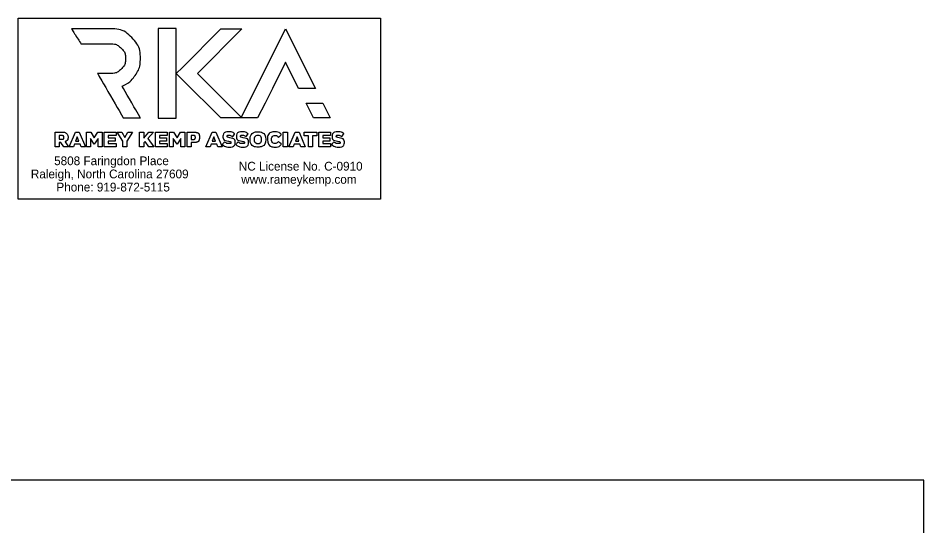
# Model space of a CAD drawing. Extents: x 573078 to 573131.9, y -55221.3 to -55195.5.
# Drawn here: x 573104.51 to 573112.01, y -55199.68 to -55195.47 of the extents above; entities that cross this region are included whole.
import ezdxf

# ---------------------------------------------------------------- set-up
doc = ezdxf.new("R2010")
doc.units = 0
for name, color, linetype in [('Old_Level_60', 7, 'Continuous'), ('Old_Level_61', 7, 'Continuous'), ('Old_Level_62', 7, 'Continuous'), ('Old_Level_63', 7, 'Continuous'), ('Sheet Plan CELL', 7, 'Continuous'), ('Sheet Plot Border Inside CELL', 7, 'Continuous')]:
    doc.layers.add(name, color=color, linetype=linetype)

msp = doc.modelspace()

# ---------------------------------------------------------------- linework, layer by layer
at = {"layer": 'Old_Level_60'}
for p, q in [((573105.8216, -55195.5551), (573105.6738, -55195.5551)), ((573105.6738, -55195.5551), (573105.6738, -55196.298)), ((573105.8216, -55196.298), (573105.8216, -55195.5551)), ((573105.8744, -55195.8777), (573106.1935, -55195.5595)), ((573106.3669, -55195.5595), (573105.998, -55195.9284)), ((573106.1935, -55195.5595), (573106.3669, -55195.5595)), ((573106.3601, -55196.2973), (573106.7289, -55195.5595)), ((573106.7289, -55195.5595), (573106.9752, -55196.052)), ((573106.7289, -55195.8352), (573106.6201, -55196.052)), ((573106.8368, -55196.052), (573106.7289, -55195.8352)), ((573105.8228, -55195.9293), (573105.8744, -55195.8777)), ((573105.8744, -55195.98), (573105.8228, -55195.9293)), ((573105.998, -55195.9284), (573106.3669, -55196.2973)), ((573106.1935, -55196.2973), (573105.8744, -55195.98)), ((573106.6201, -55196.052), (573106.5593, -55196.1737)), ((573106.9752, -55196.052), (573106.8368, -55196.052)), ((573106.5593, -55196.1737), (573106.4965, -55196.2973)), ((573105.6738, -55196.298), (573105.8216, -55196.298)), ((573106.3669, -55196.2973), (573106.1935, -55196.2973)), ((573106.4965, -55196.2973), (573106.3601, -55196.2973))]:
    msp.add_line(p, q, dxfattribs=at)
msp.add_open_spline([(573105.3748, -55196.0326), (573105.3748, -55196.0326), (573105.5261, -55196.2973), (573105.5261, -55196.2973), (573105.5261, -55196.2973), (573105.385, -55196.2973), (573105.385, -55196.2973), (573105.385, -55196.2973), (573105.171, -55195.9275), (573105.171, -55195.9275), (573105.171, -55195.9275), (573105.2807, -55195.9284), (573105.2807, -55195.9284), (573105.3139, -55195.9284), (573105.3425, -55195.9164), (573105.3665, -55195.8924), (573105.3914, -55195.8684), (573105.4034, -55195.8389), (573105.4034, -55195.8048), (573105.4034, -55195.7716), (573105.3914, -55195.743), (573105.3665, -55195.719), (573105.3425, -55195.6951), (573105.3139, -55195.6831), (573105.2807, -55195.6831), (573105.2807, -55195.6831), (573105.0345, -55195.6831), (573105.0345, -55195.6831), (573105.0345, -55195.6831), (573104.957, -55195.5595), (573104.957, -55195.5595), (573104.957, -55195.5595), (573105.2807, -55195.5595), (573105.2807, -55195.5595), (573105.3481, -55195.5595), (573105.4062, -55195.5835), (573105.4541, -55195.6314), (573105.5021, -55195.6803), (573105.5261, -55195.7375), (573105.5261, -55195.8048), (573105.5261, -55195.8564), (573105.5122, -55195.9026), (573105.4827, -55195.9441), (573105.4541, -55195.9856), (573105.4182, -55196.0151), (573105.3748, -55196.0326)], degree=3, dxfattribs=at)
at = {"layer": 'Old_Level_61'}
for p, q in [((573106.9604, -55196.2973), (573106.8996, -55196.1746)), ((573106.8996, -55196.1746), (573107.036, -55196.1746)), ((573107.036, -55196.1746), (573107.0978, -55196.2973)), ((573107.0978, -55196.2973), (573106.9604, -55196.2973))]:
    msp.add_line(p, q, dxfattribs=at)
at = {"layer": 'Old_Level_62'}
for p, q in [((573104.8933, -55196.4583), (573104.8933, -55196.458)), ((573104.9272, -55196.4559), (573104.9272, -55196.4563)), ((573104.9363, -55196.5359), (573104.9879, -55196.4136)), ((573104.9879, -55196.4136), (573105.0204, -55196.4136)), ((573105.0039, -55196.4535), (573104.9902, -55196.488)), ((573105.0174, -55196.488), (573105.0039, -55196.4535)), ((573105.0204, -55196.4136), (573105.0721, -55196.5359)), ((573105.08, -55196.4145), (573105.1156, -55196.4145)), ((573105.08, -55196.5359), (573105.08, -55196.4145)), ((573105.1156, -55196.4145), (573105.1445, -55196.4615)), ((573105.1445, -55196.4615), (573105.1735, -55196.4145)), ((573105.1735, -55196.4145), (573105.2091, -55196.4145)), ((573105.2091, -55196.4145), (573105.2091, -55196.5359)), ((573105.2267, -55196.4145), (573105.3244, -55196.4145)), ((573105.2267, -55196.5359), (573105.2267, -55196.4145)), ((573105.3244, -55196.4431), (573105.26, -55196.4431)), ((573105.26, -55196.4431), (573105.26, -55196.4615)), ((573105.3244, -55196.4145), (573105.3244, -55196.4431)), ((573105.3814, -55196.4904), (573105.3352, -55196.4145)), ((573105.3352, -55196.4145), (573105.3735, -55196.4145)), ((573105.3735, -55196.4145), (573105.3985, -55196.4587)), ((573105.3985, -55196.4587), (573105.4237, -55196.4145)), ((573105.4613, -55196.4145), (573105.4152, -55196.4899)), ((573105.4237, -55196.4145), (573105.4613, -55196.4145)), ((573105.5198, -55196.4145), (573105.5535, -55196.4145)), ((573105.5198, -55196.5359), (573105.5198, -55196.4145)), ((573105.5535, -55196.4145), (573105.5535, -55196.4637)), ((573105.5535, -55196.4637), (573105.5953, -55196.4145)), ((573105.6352, -55196.4145), (573105.5892, -55196.4667)), ((573105.5953, -55196.4145), (573105.6352, -55196.4145)), ((573105.6503, -55196.4145), (573105.748, -55196.4145)), ((573105.6503, -55196.5359), (573105.6503, -55196.4145)), ((573105.748, -55196.4431), (573105.6836, -55196.4431)), ((573105.6836, -55196.4431), (573105.6836, -55196.4615)), ((573105.748, -55196.4145), (573105.748, -55196.4431)), ((573105.766, -55196.4145), (573105.8016, -55196.4145)), ((573105.766, -55196.5359), (573105.766, -55196.4145)), ((573105.8016, -55196.4145), (573105.8306, -55196.4615)), ((573105.8306, -55196.4615), (573105.8595, -55196.4145)), ((573105.8595, -55196.4145), (573105.8951, -55196.4145)), ((573105.8951, -55196.4145), (573105.8951, -55196.5359)), ((573105.9816, -55196.459), (573105.9816, -55196.4587)), ((573106.0153, -55196.4571), (573106.0153, -55196.4575)), ((573106.0678, -55196.5359), (573106.1195, -55196.4136)), ((573106.1195, -55196.4136), (573106.152, -55196.4136)), ((573106.1355, -55196.4535), (573106.1218, -55196.488)), ((573106.149, -55196.488), (573106.1355, -55196.4535)), ((573106.152, -55196.4136), (573106.2037, -55196.5359)), ((573106.7097, -55196.4145), (573106.7436, -55196.4145)), ((573106.7097, -55196.5359), (573106.7097, -55196.4145)), ((573106.7436, -55196.4145), (573106.7436, -55196.5359)), ((573106.7561, -55196.5359), (573106.8078, -55196.4136)), ((573106.8078, -55196.4136), (573106.8402, -55196.4136)), ((573106.8237, -55196.4535), (573106.81, -55196.488)), ((573106.8373, -55196.488), (573106.8237, -55196.4535)), ((573106.8402, -55196.4136), (573106.8919, -55196.5359)), ((573106.8813, -55196.444), (573106.8813, -55196.4145)), ((573106.8813, -55196.4145), (573106.9878, -55196.4145)), ((573106.9178, -55196.444), (573106.8813, -55196.444)), ((573106.9178, -55196.5359), (573106.9178, -55196.444)), ((573106.9878, -55196.444), (573106.9514, -55196.444)), ((573106.9514, -55196.444), (573106.9514, -55196.5359)), ((573106.9878, -55196.4145), (573106.9878, -55196.444)), ((573107.0026, -55196.4145), (573107.1003, -55196.4145)), ((573107.0026, -55196.5359), (573107.0026, -55196.4145)), ((573107.1003, -55196.4431), (573107.0359, -55196.4431)), ((573107.0359, -55196.4431), (573107.0359, -55196.4615)), ((573107.1003, -55196.4145), (573107.1003, -55196.4431)), ((573104.9803, -55196.5142), (573104.9716, -55196.5359)), ((573105.0272, -55196.5142), (573104.9803, -55196.5142)), ((573104.9902, -55196.488), (573105.0174, -55196.488)), ((573105.036, -55196.5359), (573105.0272, -55196.5142)), ((573105.1438, -55196.5137), (573105.113, -55196.4665)), ((573105.113, -55196.4665), (573105.113, -55196.5359)), ((573105.1445, -55196.5137), (573105.1438, -55196.5137)), ((573105.1756, -55196.4662), (573105.1445, -55196.5137)), ((573105.1756, -55196.5359), (573105.1756, -55196.4662)), ((573105.26, -55196.4615), (573105.3183, -55196.4615)), ((573105.3183, -55196.488), (573105.26, -55196.488)), ((573105.26, -55196.488), (573105.26, -55196.5073)), ((573105.26, -55196.5073), (573105.3253, -55196.5073)), ((573105.3183, -55196.4615), (573105.3183, -55196.488)), ((573105.3253, -55196.5073), (573105.3253, -55196.5359)), ((573105.3814, -55196.5359), (573105.3814, -55196.4904)), ((573105.4152, -55196.4899), (573105.4152, -55196.5359)), ((573105.5658, -55196.4908), (573105.5535, -55196.5045)), ((573105.5535, -55196.5045), (573105.5535, -55196.5359)), ((573105.5963, -55196.5359), (573105.5658, -55196.4908)), ((573105.5892, -55196.4667), (573105.6367, -55196.5359)), ((573105.6836, -55196.4615), (573105.7419, -55196.4615)), ((573105.7419, -55196.488), (573105.6836, -55196.488)), ((573105.6836, -55196.488), (573105.6836, -55196.5073)), ((573105.6836, -55196.5073), (573105.7489, -55196.5073)), ((573105.7419, -55196.4615), (573105.7419, -55196.488)), ((573105.7489, -55196.5073), (573105.7489, -55196.5359)), ((573105.8299, -55196.5137), (573105.799, -55196.4665)), ((573105.799, -55196.4665), (573105.799, -55196.5359)), ((573105.8306, -55196.5137), (573105.8299, -55196.5137)), ((573105.8616, -55196.4662), (573105.8306, -55196.5137)), ((573105.8616, -55196.5359), (573105.8616, -55196.4662)), ((573106.1119, -55196.5142), (573106.1032, -55196.5359)), ((573106.1587, -55196.5142), (573106.1119, -55196.5142)), ((573106.1218, -55196.488), (573106.149, -55196.488)), ((573106.1676, -55196.5359), (573106.1587, -55196.5142)), ((573106.4341, -55196.4755), (573106.4341, -55196.4752)), ((573106.4686, -55196.4748), (573106.4686, -55196.4752)), ((573106.5305, -55196.4755), (573106.5305, -55196.4752)), ((573106.5649, -55196.4748), (573106.5649, -55196.4752)), ((573106.8001, -55196.5142), (573106.7915, -55196.5359)), ((573106.847, -55196.5142), (573106.8001, -55196.5142)), ((573106.81, -55196.488), (573106.8373, -55196.488)), ((573106.8558, -55196.5359), (573106.847, -55196.5142)), ((573107.0359, -55196.4615), (573107.0942, -55196.4615)), ((573107.0942, -55196.488), (573107.0359, -55196.488)), ((573107.0359, -55196.488), (573107.0359, -55196.5073)), ((573107.0359, -55196.5073), (573107.1011, -55196.5073)), ((573107.0942, -55196.4615), (573107.0942, -55196.488)), ((573107.1011, -55196.5073), (573107.1011, -55196.5359)), ((573104.9716, -55196.5359), (573104.9363, -55196.5359)), ((573105.0721, -55196.5359), (573105.036, -55196.5359)), ((573105.113, -55196.5359), (573105.08, -55196.5359)), ((573105.2091, -55196.5359), (573105.1756, -55196.5359)), ((573105.3253, -55196.5359), (573105.2267, -55196.5359)), ((573105.4152, -55196.5359), (573105.3814, -55196.5359)), ((573105.5535, -55196.5359), (573105.5198, -55196.5359)), ((573105.6367, -55196.5359), (573105.5963, -55196.5359)), ((573105.7489, -55196.5359), (573105.6503, -55196.5359)), ((573105.799, -55196.5359), (573105.766, -55196.5359)), ((573105.8951, -55196.5359), (573105.8616, -55196.5359)), ((573106.1032, -55196.5359), (573106.0678, -55196.5359)), ((573106.2037, -55196.5359), (573106.1676, -55196.5359)), ((573106.7436, -55196.5359), (573106.7097, -55196.5359)), ((573106.7915, -55196.5359), (573106.7561, -55196.5359)), ((573106.8919, -55196.5359), (573106.8558, -55196.5359)), ((573106.9514, -55196.5359), (573106.9178, -55196.5359)), ((573107.1011, -55196.5359), (573107.0026, -55196.5359))]:
    msp.add_line(p, q, dxfattribs=at)
for points in [[(573104.9022, -55196.4936), (573104.9312, -55196.5359), (573104.8923, -55196.5359), (573104.8678, -55196.4991), (573104.8675, -55196.4991), (573104.8531, -55196.4991), (573104.8531, -55196.5359), (573104.8194, -55196.5359), (573104.8194, -55196.4145), (573104.8769, -55196.4145)], [(573104.8751, -55196.4436), (573104.8531, -55196.4436), (573104.8531, -55196.4728), (573104.8753, -55196.4728)], [(573105.9631, -55196.5012), (573105.9464, -55196.5012), (573105.9464, -55196.5359), (573105.9127, -55196.5359), (573105.9127, -55196.4145), (573105.9648, -55196.4145)], [(573105.9622, -55196.4427), (573105.9464, -55196.4427), (573105.9464, -55196.4748), (573105.9624, -55196.4748)]]:
    msp.add_lwpolyline(points, dxfattribs=at)
for points, degree in [([(573104.8933, -55196.458), (573104.8933, -55196.4485), (573104.8864, -55196.4436), (573104.8751, -55196.4436)], 2), ([(573104.8753, -55196.4728), (573104.8867, -55196.4728), (573104.8933, -55196.4672), (573104.8933, -55196.4583)], 2), ([(573104.8769, -55196.4145), (573104.8954, -55196.4145), (573104.9083, -55196.4193), (573104.9164, -55196.4276), (573104.9235, -55196.4346), (573104.9272, -55196.444), (573104.9272, -55196.4559)], 3), ([(573104.9272, -55196.4563), (573104.9272, -55196.4748), (573104.9173, -55196.4871), (573104.9022, -55196.4936)], 2), ([(573105.9816, -55196.4587), (573105.9816, -55196.4483), (573105.9743, -55196.4427), (573105.9622, -55196.4427)], 2), ([(573105.9624, -55196.4748), (573105.9743, -55196.4748), (573105.9816, -55196.4686), (573105.9816, -55196.459)], 2), ([(573106.0153, -55196.4575), (573106.0153, -55196.4861), (573105.9932, -55196.5012), (573105.9631, -55196.5012)], 2), ([(573105.9648, -55196.4145), (573105.9955, -55196.4145), (573106.0153, -55196.4302), (573106.0153, -55196.4571)], 2), ([(573106.2046, -55196.5179), (573106.2046, -55196.5179), (573106.2233, -55196.4955), (573106.2233, -55196.4955), (573106.2353, -55196.505), (573106.2486, -55196.51), (573106.2627, -55196.51), (573106.2717, -55196.51), (573106.2765, -55196.5069), (573106.2765, -55196.5017), (573106.2765, -55196.5017), (573106.2765, -55196.5014), (573106.2765, -55196.5014), (573106.2765, -55196.4963), (573106.2726, -55196.4936), (573106.2561, -55196.4897), (573106.2302, -55196.4839), (573106.2103, -55196.4766), (573106.2103, -55196.4516), (573106.2103, -55196.4516), (573106.2103, -55196.4512), (573106.2103, -55196.4512), (573106.2103, -55196.4287), (573106.2281, -55196.4124), (573106.2573, -55196.4124), (573106.2779, -55196.4124), (573106.2941, -55196.4179), (573106.3073, -55196.4285), (573106.3073, -55196.4285), (573106.2904, -55196.4523), (573106.2904, -55196.4523), (573106.2793, -55196.4445), (573106.2672, -55196.4403), (573106.2564, -55196.4403), (573106.2483, -55196.4403), (573106.2443, -55196.4438), (573106.2443, -55196.4481), (573106.2443, -55196.4481), (573106.2443, -55196.4485), (573106.2443, -55196.4485), (573106.2443, -55196.454), (573106.2484, -55196.4564), (573106.2653, -55196.4603), (573106.2932, -55196.4663), (573106.3105, -55196.4754), (573106.3105, -55196.4981), (573106.3105, -55196.4981), (573106.3105, -55196.4984), (573106.3105, -55196.4984), (573106.3105, -55196.5232), (573106.2909, -55196.538), (573106.2615, -55196.538), (573106.2399, -55196.538), (573106.2195, -55196.5312), (573106.2046, -55196.5179)], 3), ([(573106.3159, -55196.5179), (573106.3159, -55196.5179), (573106.3347, -55196.4955), (573106.3347, -55196.4955), (573106.3466, -55196.505), (573106.36, -55196.51), (573106.374, -55196.51), (573106.3831, -55196.51), (573106.3879, -55196.5069), (573106.3879, -55196.5017), (573106.3879, -55196.5017), (573106.3879, -55196.5014), (573106.3879, -55196.5014), (573106.3879, -55196.4963), (573106.3839, -55196.4936), (573106.3675, -55196.4897), (573106.3416, -55196.4839), (573106.3217, -55196.4766), (573106.3217, -55196.4516), (573106.3217, -55196.4516), (573106.3217, -55196.4512), (573106.3217, -55196.4512), (573106.3217, -55196.4287), (573106.3395, -55196.4124), (573106.3687, -55196.4124), (573106.3893, -55196.4124), (573106.4054, -55196.4179), (573106.4186, -55196.4285), (573106.4186, -55196.4285), (573106.4018, -55196.4523), (573106.4018, -55196.4523), (573106.3907, -55196.4445), (573106.3786, -55196.4403), (573106.3678, -55196.4403), (573106.3596, -55196.4403), (573106.3557, -55196.4438), (573106.3557, -55196.4481), (573106.3557, -55196.4481), (573106.3557, -55196.4485), (573106.3557, -55196.4485), (573106.3557, -55196.454), (573106.3598, -55196.4564), (573106.3766, -55196.4603), (573106.4046, -55196.4663), (573106.4219, -55196.4754), (573106.4219, -55196.4981), (573106.4219, -55196.4981), (573106.4219, -55196.4984), (573106.4219, -55196.4984), (573106.4219, -55196.5232), (573106.4023, -55196.538), (573106.3728, -55196.538), (573106.3513, -55196.538), (573106.3308, -55196.5312), (573106.3159, -55196.5179)], 3), ([(573106.4341, -55196.4752), (573106.4341, -55196.4403), (573106.4622, -55196.412), (573106.4996, -55196.412), (573106.5371, -55196.412), (573106.5649, -55196.44), (573106.5649, -55196.4748)], 3), ([(573106.5305, -55196.4752), (573106.5305, -55196.4577), (573106.5179, -55196.4424), (573106.4993, -55196.4424), (573106.4809, -55196.4424), (573106.4686, -55196.4573), (573106.4686, -55196.4748)], 3), ([(573106.5782, -55196.4755), (573106.5782, -55196.4755), (573106.5782, -55196.4752), (573106.5782, -55196.4752), (573106.5782, -55196.4398), (573106.6055, -55196.412), (573106.6423, -55196.412), (573106.6671, -55196.412), (573106.683, -55196.4224), (573106.6938, -55196.4374), (573106.6938, -55196.4374), (573106.6685, -55196.457), (573106.6685, -55196.457), (573106.6615, -55196.4483), (573106.6535, -55196.4427), (573106.6419, -55196.4427), (573106.6249, -55196.4427), (573106.6129, -55196.4571), (573106.6129, -55196.4748), (573106.6129, -55196.4748), (573106.6129, -55196.4752), (573106.6129, -55196.4752), (573106.6129, -55196.4934), (573106.6249, -55196.5076), (573106.6419, -55196.5076), (573106.6546, -55196.5076), (573106.662, -55196.5017), (573106.6693, -55196.4929), (573106.6693, -55196.4929), (573106.6946, -55196.5109), (573106.6946, -55196.5109), (573106.6832, -55196.5267), (573106.6678, -55196.5383), (573106.6409, -55196.5383), (573106.6062, -55196.5383), (573106.5782, -55196.5118), (573106.5782, -55196.4755)], 3), ([(573107.1091, -55196.5179), (573107.1091, -55196.5179), (573107.1278, -55196.4955), (573107.1278, -55196.4955), (573107.1398, -55196.505), (573107.1532, -55196.51), (573107.1672, -55196.51), (573107.1763, -55196.51), (573107.1811, -55196.5069), (573107.1811, -55196.5017), (573107.1811, -55196.5017), (573107.1811, -55196.5014), (573107.1811, -55196.5014), (573107.1811, -55196.4963), (573107.1771, -55196.4936), (573107.1606, -55196.4897), (573107.1348, -55196.4839), (573107.1148, -55196.4766), (573107.1148, -55196.4516), (573107.1148, -55196.4516), (573107.1148, -55196.4512), (573107.1148, -55196.4512), (573107.1148, -55196.4287), (573107.1327, -55196.4124), (573107.1618, -55196.4124), (573107.1825, -55196.4124), (573107.1986, -55196.4179), (573107.2118, -55196.4285), (573107.2118, -55196.4285), (573107.195, -55196.4523), (573107.195, -55196.4523), (573107.1839, -55196.4445), (573107.1717, -55196.4403), (573107.161, -55196.4403), (573107.1528, -55196.4403), (573107.1488, -55196.4438), (573107.1488, -55196.4481), (573107.1488, -55196.4481), (573107.1488, -55196.4485), (573107.1488, -55196.4485), (573107.1488, -55196.454), (573107.153, -55196.4564), (573107.1698, -55196.4603), (573107.1978, -55196.4663), (573107.2151, -55196.4754), (573107.2151, -55196.4981), (573107.2151, -55196.4981), (573107.2151, -55196.4984), (573107.2151, -55196.4984), (573107.2151, -55196.5232), (573107.1955, -55196.538), (573107.166, -55196.538), (573107.1445, -55196.538), (573107.124, -55196.5312), (573107.1091, -55196.5179)], 3), ([(573106.5649, -55196.4752), (573106.5649, -55196.51), (573106.5368, -55196.5383), (573106.4993, -55196.5383), (573106.4618, -55196.5383), (573106.4341, -55196.5104), (573106.4341, -55196.4755)], 3), ([(573106.4686, -55196.4752), (573106.4686, -55196.4927), (573106.4813, -55196.508), (573106.4996, -55196.508), (573106.5182, -55196.508), (573106.5305, -55196.493), (573106.5305, -55196.4755)], 3)]:
    msp.add_open_spline(points, degree=degree, dxfattribs=at)
at = {"layer": 'Sheet Plan CELL'}
msp.add_lwpolyline([(573107.5142, -55196.9698), (573104.5142, -55196.9698), (573104.5142, -55195.4698), (573107.5142, -55195.4698)], close=True, dxfattribs=at)
at = {"layer": 'Sheet Plot Border Inside CELL'}
msp.add_lwpolyline([(573112.0142, -55199.2984), (573078.0142, -55199.2984), (573078.0142, -55221.2984), (573112.0142, -55221.2984)], close=True, dxfattribs=at)

# ---------------------------------------------------------------- texts
at = {"layer": 'Old_Level_63'}
for s, p in [('5808 Faringdon Place', (573104.8119, -55196.6883)), ('NC License No. C-0910', (573106.3412, -55196.7331)), ('Raleigh, North Carolina 27609', (573104.6194, -55196.7972)), ('Phone: 919-872-5115', (573104.831, -55196.9061)), ('www.rameykemp.com', (573106.3616, -55196.842))]:
    msp.add_text(s, height=0.0726, dxfattribs=at).set_placement(p)

doc.saveas('drawing.dxf')
